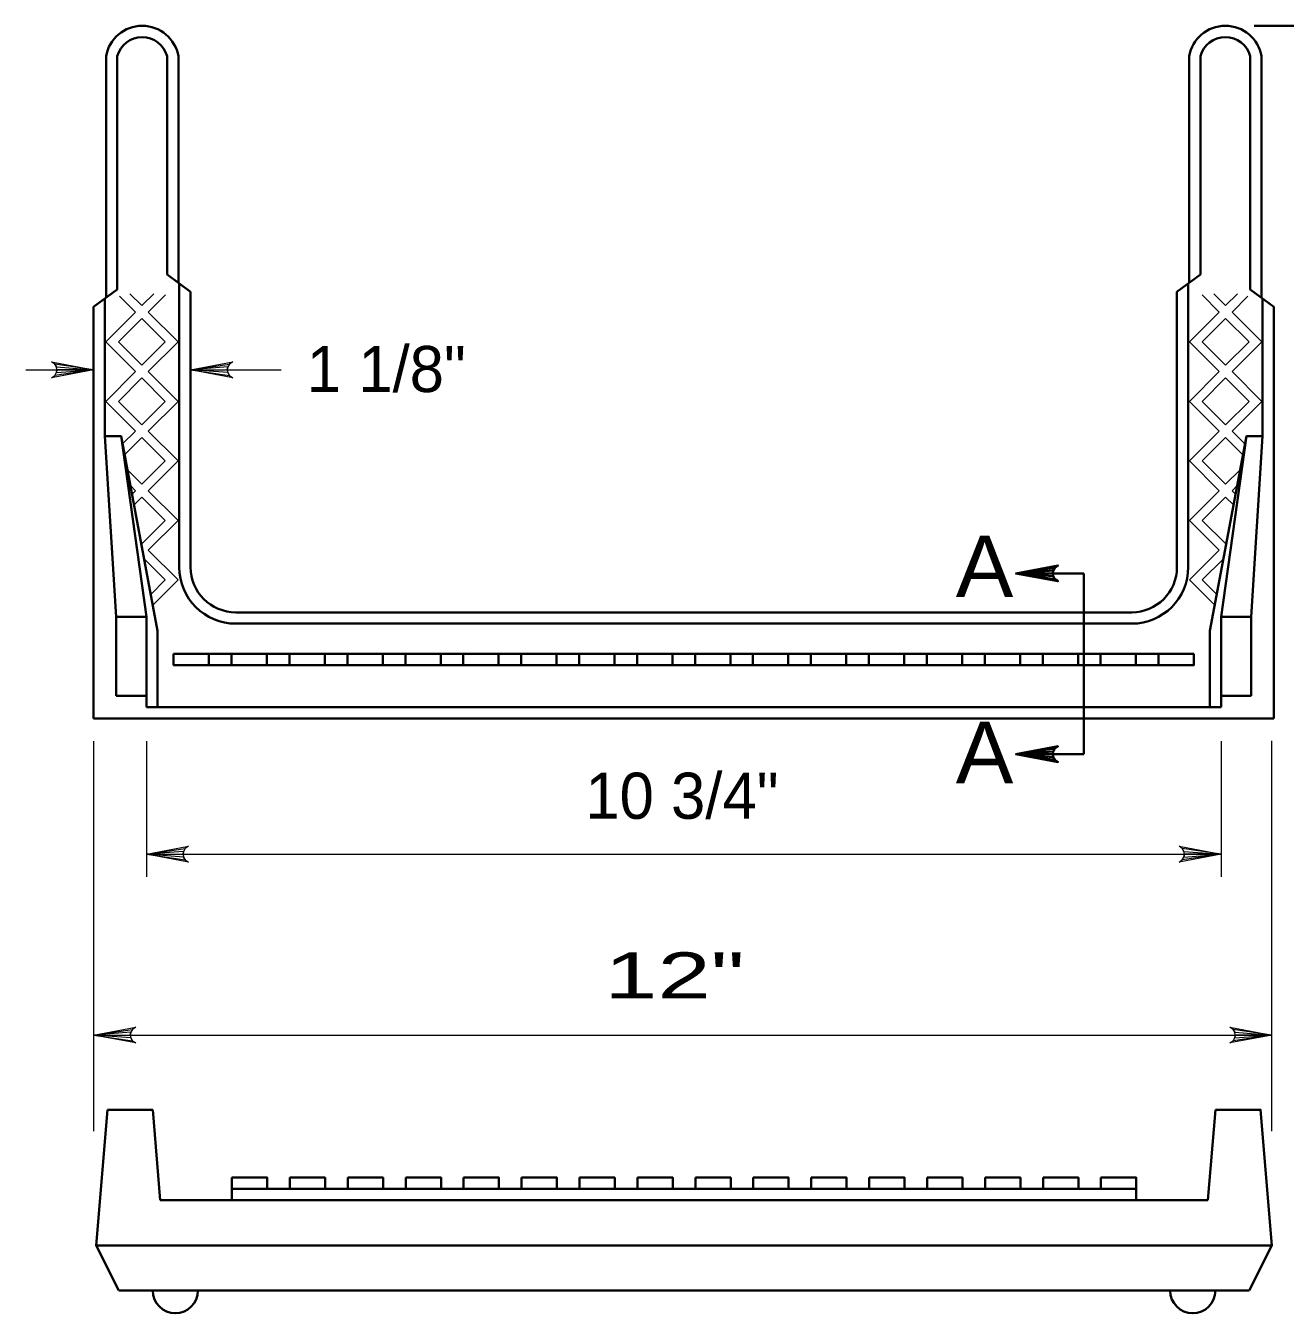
# Model space of a CAD drawing. Extents: x 15 to 140, y -57 to 117.
# Drawn here: x 85.64 to 113.5, y 80.88 to 109.35 of the extents above; entities that cross this region are included whole.
import ezdxf
from ezdxf.enums import TextEntityAlignment as Align

# ---------------------------------------------------------------- set-up
doc = ezdxf.new("R2010")
doc.units = 0
doc.header["$LTSCALE"] = 0.41
for name, color, linetype, lineweight in [('1', 7, 'Continuous', 35), ('10', 7, 'Continuous', 13), ('12', 7, 'Continuous', 53), ('13', 7, 'Continuous', 53), ('6', 7, 'Continuous', 13)]:
    doc.layers.add(name, color=color, linetype=linetype, lineweight=lineweight)

msp = doc.modelspace()

# ---------------------------------------------------------------- linework, layer by layer
at = {"layer": '1'}
for p, q in [((112.8121, 109.3527), (122.5672, 109.3527)), ((87.4195, 103.3354), (87.4195, 108.6773)), ((87.6695, 103.5203), (87.6695, 108.6773)), ((88.7695, 103.8541), (88.7695, 108.6773)), ((89.0195, 103.6692), (89.0195, 108.6773)), ((111.3721, 103.6692), (111.3721, 108.6773)), ((111.6221, 103.8541), (111.6221, 108.6773)), ((112.7221, 103.5203), (112.7221, 108.6773)), ((112.9721, 103.3354), (112.9721, 108.6773)), ((88.7695, 103.8541), (89.2897, 103.4694)), ((111.6221, 103.8541), (111.1019, 103.4694)), ((87.6695, 103.5203), (87.1445, 103.132)), ((89.0397, 97.3782), (89.0397, 103.6543)), ((89.2897, 97.3782), (89.2897, 103.4694)), ((111.1019, 97.3782), (111.1019, 103.4694)), ((111.3519, 97.3782), (111.3519, 103.6543)), ((112.7221, 103.5203), (113.2471, 103.132)), ((87.1445, 94.0282), (87.1445, 103.132)), ((87.3945, 100.2782), (87.3945, 103.3169)), ((112.9971, 100.2782), (112.9971, 103.3169)), ((113.2471, 94.0282), (113.2471, 103.132)), ((87.3945, 100.2782), (87.7542, 100.2782)), ((87.3945, 100.2782), (87.6445, 96.2782)), ((87.7537, 100.2817), (88.3115, 96.2782)), ((87.7542, 100.2782), (88.5615, 95.9675)), ((112.6374, 100.2782), (111.8301, 95.9675)), ((112.6379, 100.2817), (112.0801, 96.2782)), ((112.9971, 100.2782), (112.6374, 100.2782)), ((112.9971, 100.2782), (112.7471, 96.2782)), ((87.6445, 96.2782), (88.3115, 96.2782)), ((87.6445, 94.5282), (87.6445, 96.2782)), ((88.3115, 94.2782), (88.3115, 96.2782)), ((90.2897, 96.3782), (110.1019, 96.3782)), ((112.7471, 96.2782), (112.0801, 96.2782)), ((112.0801, 94.2782), (112.0801, 96.2782)), ((112.7471, 94.5282), (112.7471, 96.2782)), ((90.2897, 96.1282), (110.1019, 96.1282)), ((88.5615, 94.2782), (88.5615, 95.9675)), ((111.8301, 94.2782), (111.8301, 95.9675)), ((88.9145, 95.462), (111.4771, 95.462)), ((90.1958, 95.212), (90.1958, 95.462)), ((98.6649, 95.212), (98.6649, 95.462)), ((101.7267, 95.212), (101.7267, 95.462)), ((110.1958, 95.212), (110.1958, 95.462)), ((88.9145, 95.212), (111.4771, 95.212)), ((87.6445, 94.5282), (88.3115, 94.5282)), ((88.3115, 94.2782), (112.0801, 94.2782)), ((112.7471, 94.5282), (112.0801, 94.5282)), ((87.1445, 94.0282), (113.2471, 94.0282)), ((87.4522, 85.3754), (87.2022, 82.3754)), ((87.4522, 85.3754), (88.4522, 85.3754)), ((88.4522, 85.3754), (88.6189, 83.3754)), ((111.9522, 85.3754), (111.7856, 83.3754)), ((98.6713, 83.6254), (98.6713, 83.8754)), ((110.2022, 83.3754), (110.2022, 83.8754)), ((90.2022, 83.6254), (110.2022, 83.6254)), ((88.6189, 83.3754), (111.7856, 83.3754)), ((87.2022, 82.3754), (113.2022, 82.3754)), ((87.2022, 82.3754), (87.7022, 81.3754)), ((113.2022, 82.3754), (112.7022, 81.3754)), ((87.7022, 81.3754), (112.7022, 81.3754))]:
    msp.add_line(p, q, dxfattribs=at)
for points in [[(88.9145, 95.462), (89.6958, 95.462), (89.6958, 95.212), (88.9145, 95.212)], [(90.1958, 95.462), (90.9771, 95.462), (90.9771, 95.212), (90.1958, 95.212)], [(91.4771, 95.462), (92.2584, 95.462), (92.2584, 95.212), (91.4771, 95.212)], [(92.7584, 95.462), (93.5397, 95.462), (93.5397, 95.212), (92.7584, 95.212)], [(94.0397, 95.462), (94.821, 95.462), (94.821, 95.212), (94.0397, 95.212)], [(95.321, 95.462), (96.1023, 95.462), (96.1023, 95.212), (95.321, 95.212)], [(96.6023, 95.462), (97.3836, 95.462), (97.3836, 95.212), (96.6023, 95.212)], [(97.8836, 95.462), (98.6649, 95.462), (98.6649, 95.212), (97.8836, 95.212)], [(99.1649, 95.462), (99.9462, 95.462), (99.9462, 95.212), (99.1649, 95.212)], [(101.2267, 95.462), (100.4454, 95.462), (100.4454, 95.212), (101.2267, 95.212)], [(102.508, 95.462), (101.7267, 95.462), (101.7267, 95.212), (102.508, 95.212)], [(103.7893, 95.462), (103.008, 95.462), (103.008, 95.212), (103.7893, 95.212)], [(105.0706, 95.462), (104.2893, 95.462), (104.2893, 95.212), (105.0706, 95.212)], [(106.3519, 95.462), (105.5706, 95.462), (105.5706, 95.212), (106.3519, 95.212)], [(107.6332, 95.462), (106.8519, 95.462), (106.8519, 95.212), (107.6332, 95.212)], [(108.9145, 95.462), (108.1332, 95.462), (108.1332, 95.212), (108.9145, 95.212)], [(110.1958, 95.462), (109.4145, 95.462), (109.4145, 95.212), (110.1958, 95.212)], [(111.4771, 95.462), (110.6958, 95.462), (110.6958, 95.212), (111.4771, 95.212)], [(90.2022, 83.8754), (90.9835, 83.8754), (90.9835, 83.6254), (90.2022, 83.6254)], [(91.4835, 83.8754), (92.2648, 83.8754), (92.2648, 83.6254), (91.4835, 83.6254)], [(92.7648, 83.8754), (93.5461, 83.8754), (93.5461, 83.6254), (92.7648, 83.6254)], [(94.0461, 83.8754), (94.8274, 83.8754), (94.8274, 83.6254), (94.0461, 83.6254)], [(95.3274, 83.8754), (96.1087, 83.8754), (96.1087, 83.6254), (95.3274, 83.6254)], [(96.6087, 83.8754), (97.39, 83.8754), (97.39, 83.6254), (96.6087, 83.6254)], [(97.89, 83.8754), (98.6713, 83.8754), (98.6713, 83.6254), (97.89, 83.6254)], [(99.1713, 83.8754), (99.9526, 83.8754), (99.9526, 83.6254), (99.1713, 83.6254)], [(100.4526, 83.8754), (101.2339, 83.8754), (101.2339, 83.6254), (100.4526, 83.6254)], [(101.7339, 83.8754), (102.5152, 83.8754), (102.5152, 83.6254), (101.7339, 83.6254)], [(103.0152, 83.8754), (103.7965, 83.8754), (103.7965, 83.6254), (103.0152, 83.6254)], [(104.2965, 83.8754), (105.0778, 83.8754), (105.0778, 83.6254), (104.2965, 83.6254)], [(105.5778, 83.8754), (106.3591, 83.8754), (106.3591, 83.6254), (105.5778, 83.6254)], [(106.8591, 83.8754), (107.6404, 83.8754), (107.6404, 83.6254), (106.8591, 83.6254)], [(108.1404, 83.8754), (108.9217, 83.8754), (108.9217, 83.6254), (108.1404, 83.6254)], [(109.4209, 83.8754), (110.2022, 83.8754), (110.2022, 83.6254), (109.4209, 83.6254)]]:
    msp.add_lwpolyline(points, close=True, dxfattribs=at)
for points in [[(111.9522, 85.3754), (112.9522, 85.3754), (113.2022, 82.3754)], [(90.2022, 83.3754), (90.2022, 83.6254), (90.2022, 83.8754)]]:
    msp.add_lwpolyline(points, dxfattribs=at)
for centre, radius, start, end in [((88.2195, 108.5412), 0.8115, 9.65576, 170.34424), ((88.2195, 108.5344), 0.5683, 14.56126, 165.43874), ((112.1721, 108.5412), 0.8115, 9.65576, 170.34424), ((112.1721, 108.5344), 0.5683, 14.56126, 165.43874), ((90.2897, 97.3782), 1.25, 180, 270), ((90.2897, 97.3782), 1, 180, 270), ((110.1019, 97.3782), 1, 270, 0), ((110.1019, 97.3782), 1.25, 270, 0), ((88.9522, 81.3754), 0.5, 180, 0), ((111.4522, 81.3754), 0.5, 180, 0)]:
    msp.add_arc(centre, radius, start, end, dxfattribs=at)
at = {"layer": '10'}
for p, q in [((85.6445, 101.7427), (87.1445, 101.7427)), ((89.2897, 101.7427), (91.2897, 101.7427)), ((87.1445, 93.5282), (87.1445, 84.9006)), ((88.3115, 93.5282), (88.3115, 90.5282)), ((112.0801, 93.5282), (112.0801, 90.5282)), ((113.2022, 84.9006), (113.2022, 93.5329)), ((88.3115, 91.0282), (112.0801, 91.0282)), ((87.1445, 87.0282), (113.2022, 87.0282))]:
    msp.add_line(p, q, dxfattribs=at)
at = {"layer": '10', "lineweight": 35}
for p, q in [((107.5414, 97.2405), (109.0414, 97.2405)), ((109.0414, 97.2405), (109.0414, 93.2405)), ((107.5414, 93.2405), (109.0414, 93.2405))]:
    msp.add_line(p, q, dxfattribs=at)
at = {"layer": '10'}
for points in [[(87.1445, 101.7427), (86.2124, 101.5679), (86.2843, 101.6177), (86.3213, 101.6802), (86.332, 101.7427), (86.3213, 101.8052), (86.2843, 101.8677), (86.2124, 101.9174), (87.1445, 101.7427), (86.2843, 101.8677), (86.3213, 101.8052), (87.1445, 101.7427), (86.332, 101.7427), (86.3213, 101.6802), (87.1445, 101.7427), (86.2843, 101.6177)], [(89.2897, 101.7427), (90.2218, 101.9174), (90.1499, 101.8677), (90.1129, 101.8052), (90.1022, 101.7427), (90.1129, 101.6802), (90.1499, 101.6177), (90.2218, 101.5679), (89.2897, 101.7427), (90.1499, 101.6177), (90.1129, 101.6802), (89.2897, 101.7427), (90.1022, 101.7427), (90.1129, 101.8052), (89.2897, 101.7427), (90.1499, 101.8677)], [(88.3115, 91.0282), (89.2436, 91.203), (89.1718, 91.1532), (89.1347, 91.0907), (89.124, 91.0282), (89.1347, 90.9657), (89.1718, 90.9032), (89.2436, 90.8535), (88.3115, 91.0282), (89.1718, 90.9032), (89.1347, 90.9657), (88.3115, 91.0282), (89.124, 91.0282), (89.1347, 91.0907), (88.3115, 91.0282), (89.1718, 91.1532)], [(112.0801, 91.0282), (111.148, 90.8535), (111.2198, 90.9032), (111.2569, 90.9657), (111.2676, 91.0282), (111.2569, 91.0907), (111.2198, 91.1532), (111.148, 91.203), (112.0801, 91.0282), (111.2198, 91.1532), (111.2569, 91.0907), (112.0801, 91.0282), (111.2676, 91.0282), (111.2569, 90.9657), (112.0801, 91.0282), (111.2198, 90.9032)], [(87.1445, 87.0282), (88.0766, 87.203), (88.0048, 87.1532), (87.9677, 87.0907), (87.957, 87.0282), (87.9677, 86.9657), (88.0048, 86.9032), (88.0766, 86.8535), (87.1445, 87.0282), (88.0048, 86.9032), (87.9677, 86.9657), (87.1445, 87.0282), (87.957, 87.0282), (87.9677, 87.0907), (87.1445, 87.0282), (88.0048, 87.1532)], [(113.2022, 87.0282), (112.2701, 86.8535), (112.342, 86.9032), (112.379, 86.9657), (112.3897, 87.0282), (112.379, 87.0907), (112.342, 87.1532), (112.2701, 87.203), (113.2022, 87.0282), (112.342, 87.1532), (112.379, 87.0907), (113.2022, 87.0282), (112.3897, 87.0282), (112.379, 86.9657), (113.2022, 87.0282), (112.342, 86.9032)]]:
    msp.add_lwpolyline(points, dxfattribs=at)
at = {"layer": '10', "lineweight": 35}
for points in [[(107.5414, 97.2405), (108.4735, 97.4153), (108.4017, 97.3655), (108.3646, 97.303), (108.3539, 97.2405), (108.3646, 97.178), (108.4017, 97.1155), (108.4735, 97.0657), (107.5414, 97.2405), (108.4017, 97.1155), (108.3646, 97.178), (107.5414, 97.2405), (108.3539, 97.2405), (108.3646, 97.303), (107.5414, 97.2405), (108.4017, 97.3655)], [(107.5414, 93.2405), (108.4735, 93.4153), (108.4017, 93.3655), (108.3646, 93.303), (108.3539, 93.2405), (108.3646, 93.178), (108.4017, 93.1155), (108.4735, 93.0657), (107.5414, 93.2405), (108.4017, 93.1155), (108.3646, 93.178), (107.5414, 93.2405), (108.3539, 93.2405), (108.3646, 93.303), (107.5414, 93.2405), (108.4017, 93.3655)]]:
    msp.add_lwpolyline(points, dxfattribs=at)
at = {"layer": '6'}
for p, q in [((87.9484, 103.4267), (88.2128, 103.1623)), ((88.474, 103.4235), (88.2128, 103.1623)), ((88.733, 103.3997), (88.3542, 103.0209)), ((111.6586, 103.3997), (112.0374, 103.0209)), ((111.9176, 103.4235), (112.1788, 103.1623)), ((112.4432, 103.4267), (112.1788, 103.1623)), ((87.7202, 103.3721), (88.0714, 103.0209)), ((112.6714, 103.3721), (112.3202, 103.0209)), ((88.0714, 103.0209), (87.4128, 102.3623)), ((88.2128, 102.8795), (87.6956, 102.3623)), ((88.2128, 102.8795), (88.73, 102.3623)), ((88.3542, 103.0209), (89.0128, 102.3623)), ((112.0374, 103.0209), (111.3788, 102.3623)), ((112.1788, 102.8795), (111.6616, 102.3623)), ((112.1788, 102.8795), (112.696, 102.3623)), ((112.3202, 103.0209), (112.9788, 102.3623)), ((88.0714, 101.7037), (87.4128, 102.3623)), ((88.2128, 101.8452), (87.6956, 102.3623)), ((88.73, 102.3623), (88.2128, 101.8452)), ((89.0128, 102.3623), (88.3542, 101.7037)), ((111.3788, 102.3623), (112.0374, 101.7037)), ((111.6616, 102.3623), (112.1788, 101.8452)), ((112.1788, 101.8452), (112.696, 102.3623)), ((112.3202, 101.7037), (112.9788, 102.3623)), ((88.0714, 101.7037), (87.4128, 101.0452)), ((89.0128, 101.0452), (88.3542, 101.7037)), ((111.3788, 101.0452), (112.0374, 101.7037)), ((112.3202, 101.7037), (112.9788, 101.0452)), ((88.2128, 101.5623), (87.6956, 101.0451)), ((88.73, 101.0452), (88.2128, 101.5623)), ((111.6616, 101.0452), (112.1788, 101.5623)), ((112.1788, 101.5623), (112.696, 101.0451)), ((88.0714, 100.3866), (87.4128, 101.0452)), ((88.2128, 100.528), (87.6956, 101.0451)), ((88.73, 101.0452), (88.2128, 100.528)), ((89.0128, 101.0452), (88.3542, 100.3866)), ((111.3788, 101.0452), (112.0374, 100.3866)), ((111.6616, 101.0452), (112.1788, 100.528)), ((112.1788, 100.528), (112.696, 101.0451)), ((112.3202, 100.3866), (112.9788, 101.0452)), ((88.0714, 100.3866), (87.7797, 100.0949)), ((88.2128, 100.2452), (87.8318, 99.8641)), ((88.73, 99.728), (88.2128, 100.2452)), ((89.0128, 99.728), (88.3542, 100.3866)), ((111.3788, 99.728), (112.0374, 100.3866)), ((111.6616, 99.728), (112.1788, 100.2452)), ((112.1788, 100.2452), (112.5598, 99.8641)), ((112.3202, 100.3866), (112.6119, 100.0949)), ((88.73, 99.728), (88.2128, 99.2108)), ((89.0128, 99.728), (88.3542, 99.0694)), ((111.3788, 99.728), (112.0374, 99.0694)), ((111.6616, 99.728), (112.1788, 99.2108)), ((88.2128, 99.2108), (87.8945, 99.5291)), ((112.1788, 99.2108), (112.4971, 99.5291)), ((88.0714, 99.0694), (87.9597, 99.1811)), ((112.3202, 99.0694), (112.4319, 99.1811)), ((88.0714, 99.0694), (87.9949, 98.993)), ((88.2128, 98.928), (88.0395, 98.7547)), ((88.7299, 98.4108), (88.2128, 98.928)), ((89.0128, 98.4108), (88.3542, 99.0694)), ((111.3788, 98.4108), (112.0374, 99.0694)), ((111.6617, 98.4108), (112.1788, 98.928)), ((112.1788, 98.928), (112.3521, 98.7547)), ((112.3202, 99.0694), (112.3967, 98.993)), ((88.7299, 98.4108), (88.2027, 97.8836)), ((89.0128, 98.4108), (88.3542, 97.7523)), ((111.3788, 98.4108), (112.0374, 97.7523)), ((111.6617, 98.4108), (112.1889, 97.8836)), ((89.0128, 97.0937), (88.3542, 97.7523)), ((111.3788, 97.0937), (112.0374, 97.7523)), ((88.7299, 97.0937), (88.2632, 97.5604)), ((111.6617, 97.0937), (112.1284, 97.5604)), ((88.7299, 97.0937), (88.4104, 96.7742)), ((89.0128, 97.0937), (88.4551, 96.5359)), ((111.3788, 97.0937), (111.9366, 96.5359)), ((111.6617, 97.0937), (111.9812, 96.7742))]:
    msp.add_line(p, q, dxfattribs=at)

# ---------------------------------------------------------------- texts
at = {"layer": '12', "width": 1.05}
for p in [(106.8473, 96.7149), (106.8473, 92.5972)]:
    msp.add_text('A', height=1.36, dxfattribs=at).set_placement(p, align=Align.CENTER)
at = {"layer": '13'}
for s, p in [('1 1/8"', (93.6184, 101.2506)), ('10 3/4"', (100.1556, 91.8119))]:
    msp.add_text(s, height=1.02, dxfattribs=at).set_placement(p, align=Align.CENTER)
at = {"layer": '13', "width": 1.55}
msp.add_text('12"', height=1.02, dxfattribs=at).set_placement((99.9901, 87.8377), align=Align.CENTER)

doc.saveas('drawing.dxf')
